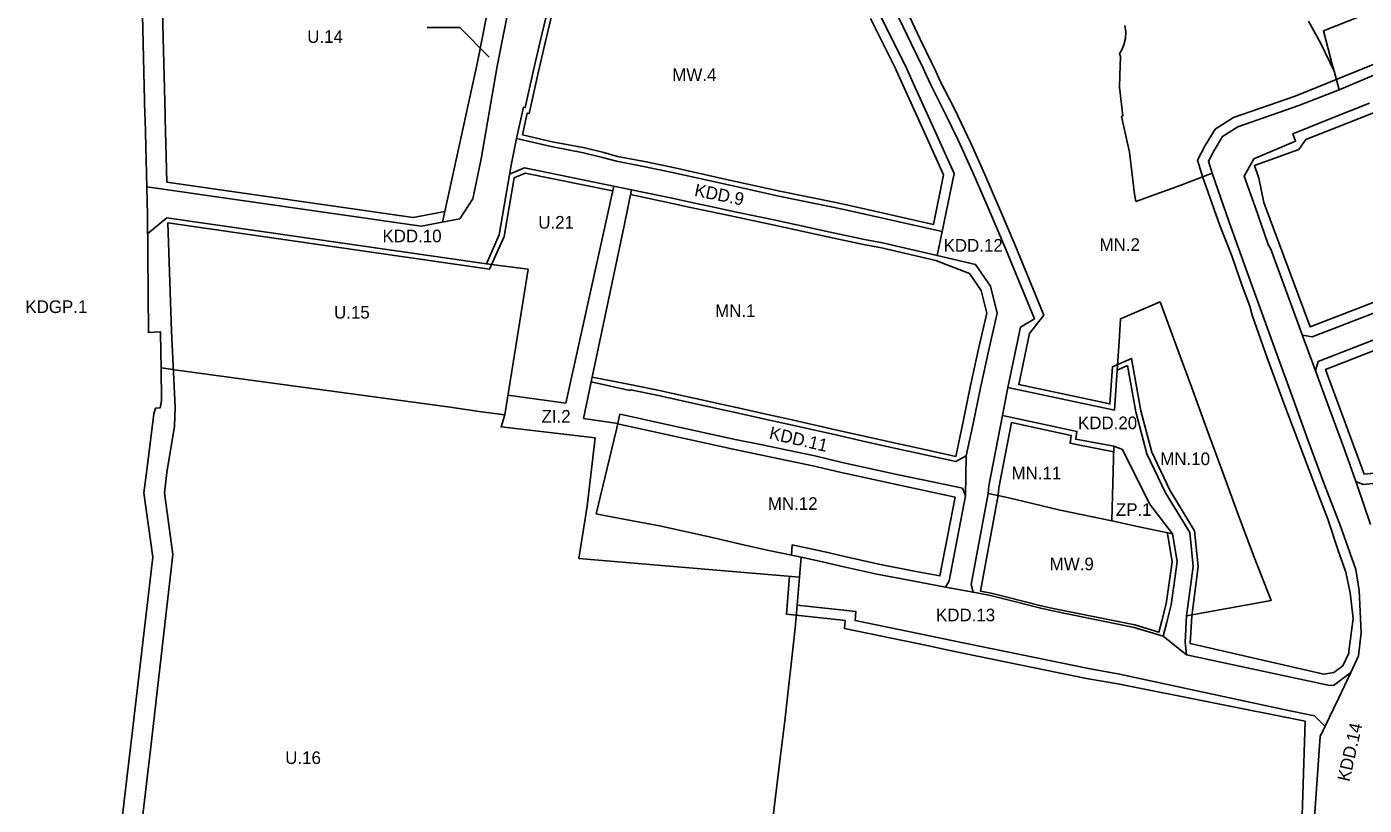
# Model space of a CAD drawing. Extents: x 7428112 to 7429828, y 5548245 to 5549272.
# Drawn here: x 7428745 to 7429274, y 5548641 to 5548949 of the extents above; entities that cross this region are included whole.
import ezdxf

# ---------------------------------------------------------------- set-up
doc = ezdxf.new("R2010")
doc.units = 0
for name, color, linetype in [('LIN_Linia Zabudowy Nieprzekraczalna', 7, 'Continuous'), ('LIN_Linia Zabudowy Obowiązujaca', 7, 'Continuous'), ('LIN_linie_rozgraniczajace', 7, 'Continuous'), ('TXT_oznaczenia_przeznaczen', 7, 'Continuous')]:
    doc.layers.add(name, color=color, linetype=linetype)

msp = doc.modelspace()

# ---------------------------------------------------------------- linework, layer by layer
at = {"layer": 'LIN_Linia Zabudowy Nieprzekraczalna'}
for points in [[(7428952.41, 5548952.95), (7428949.72, 5548941.91), (7428947.26, 5548931.07), (7428943.54, 5548914.42), (7428942.78, 5548914.57), (7428940.96, 5548905.98), (7428952.71, 5548903.26), (7428965.53, 5548900.79), (7428973.08, 5548899), (7428978.56, 5548897.44), (7428989.23, 5548895.36), (7429000.01, 5548893.17), (7429021.64, 5548888.35), (7429042.82, 5548883.66), (7429064.87, 5548879.21), (7429073.94, 5548877.18), (7429103.54, 5548870.51)], [(7429091.97, 5548957.24), (7429098.37, 5548943.91), (7429103.07, 5548934.11), (7429104.37, 5548931.39), (7429106.09, 5548927.52), (7429111.98, 5548915.99), (7429117.02, 5548905.51), (7429118.48, 5548902.35), (7429123.93, 5548890.29), (7429129.7, 5548876.77), (7429135.73, 5548862.5), (7429147.22, 5548834.62), (7429141.55, 5548827.32), (7429137.36, 5548807.14), (7429173.44, 5548799.47), (7429174.4, 5548814.14), (7429181.97, 5548817.47), (7429185.61, 5548796.76), (7429189.96, 5548780.41), (7429197.18, 5548765.35)], [(7429103.54, 5548870.51), (7429107.57, 5548890.15), (7429099.91, 5548907.12), (7429092.03, 5548924.54), (7429088.83, 5548931.62), (7429088.89, 5548931.48), (7429078.59, 5548952.07)], [(7429197.17, 5548765.34), (7429206.93, 5548749.19), (7429208.32, 5548735.11), (7429205.78, 5548715.37), (7429205.15, 5548704.66), (7429258.13, 5548692.49), (7429262.07, 5548693.19), (7429265.55, 5548695.78), (7429267.95, 5548700.83), (7429268.02, 5548701.41), (7429269.69, 5548714.47), (7429268.55, 5548724.63), (7429266.8, 5548732.91), (7429263.77, 5548741.48), (7429259.68, 5548753.78), (7429256.37, 5548762.47), (7429241.9, 5548800.77), (7429235.71, 5548817.76), (7429229.71, 5548834.54), (7429228.83, 5548838.13), (7429225.76, 5548846.21), (7429221.66, 5548858.14), (7429216.9, 5548870.06), (7429210.08, 5548889.5), (7429208.06, 5548896.01), (7429211.17, 5548901.7), (7429215.06, 5548908.2), (7429222.32, 5548912.81), (7429246.76, 5548921.31), (7429270.43, 5548930.94), (7429282.75, 5548935.89)], [(7429293.13, 5548920.77), (7429250.94, 5548904.12), (7429248.16, 5548900.12), (7429230.58, 5548893.78), (7429232.38, 5548888.78), (7429234.4, 5548879.13), (7429252.69, 5548829.93), (7429281.75, 5548841.19)], [(7428976.58, 5548883.75), (7428941.9, 5548890.86), (7428937.6, 5548888.95), (7428933.66, 5548865.79), (7428927.89, 5548852.76), (7428800.51, 5548871.09), (7428801.95, 5548828.23), (7428803.37, 5548798.18), (7428803.16, 5548790.62), (7428800.14, 5548772.25), (7428799.14, 5548764.28), (7428802.54, 5548739.84), (7428793.64, 5548662.49), (7428784.91, 5548588.83)], [(7428800.15, 5548887.3), (7428897.67, 5548873.26), (7428910.15, 5548875.65)], [(7428968.51, 5548810.1), (7428982.07, 5548807.37), (7428984.75, 5548806.9), (7428995.12, 5548804.74), (7428999.78, 5548803.7), (7429014.73, 5548800.43), (7429021.31, 5548798.96), (7429025.02, 5548798.13), (7429036.73, 5548795.54), (7429046.42, 5548793.4), (7429064.85, 5548789.26), (7429077.29, 5548786.36), (7429089.78, 5548783.68), (7429094.68, 5548782.61), (7429112.46, 5548778.7), (7429115.25, 5548791.87), (7429118.25, 5548806.7), (7429121.58, 5548821.76), (7429124.65, 5548835.38), (7429122.39, 5548844.4), (7429117.82, 5548851.13), (7429104.55, 5548856.25), (7429082.97, 5548861.22), (7429075.92, 5548862.55), (7429062.32, 5548865.5), (7429039.97, 5548870.33), (7429022.68, 5548873.99), (7429015.08, 5548875.62), (7429007.44, 5548877.24), (7428999.67, 5548878.88), (7428983.64, 5548882.3)], [(7429273.99, 5548771.63), (7429309.58, 5548775.34), (7429327.36, 5548777.91), (7429341.97, 5548778.88), (7429346.25, 5548778.91), (7429365.33, 5548778.23), (7429395.07, 5548776.65), (7429395.94, 5548791.78), (7429396.25, 5548798.38), (7429396.88, 5548810.65), (7429398.13, 5548829.54), (7429398.89, 5548843.94), (7429359.73, 5548846.77), (7429348.57, 5548847.59), (7429341.93, 5548845.59), (7429332.58, 5548841.75), (7429312.81, 5548833.85), (7429290.54, 5548825.46), (7429258.77, 5548813.12), (7429269.98, 5548782.77), (7429273.99, 5548771.63)], [(7429047.33, 5548739.59), (7429047.67, 5548743.63), (7429060.53, 5548740.86), (7429069, 5548738.93), (7429081.94, 5548736), (7429095.96, 5548733.31), (7429106.13, 5548731.39), (7429112.1, 5548762.6), (7429102.41, 5548764.65), (7429088.89, 5548767.53), (7429066.54, 5548772.43), (7429055.78, 5548774.94), (7429045.63, 5548777.11), (7429034.95, 5548779.31), (7429024.24, 5548781.52), (7429002.63, 5548786.26), (7428991.78, 5548788.62), (7428978.55, 5548791.52)], [(7429174.9, 5548780.49), (7429159.53, 5548783.53), (7429157.62, 5548783.89), (7429158.1, 5548787.01), (7429145.22, 5548789.75), (7429134.47, 5548792.08), (7429129.44, 5548766.22), (7429129.24, 5548763.4), (7429122.13, 5548725.35), (7429126.41, 5548724.56), (7429132.25, 5548723.08), (7429146.26, 5548719.55), (7429151.59, 5548718.37), (7429183.24, 5548711.96), (7429192.83, 5548709.08), (7429194.01, 5548713.59), (7429194, 5548713.58), (7429195.74, 5548720.27), (7429196.78, 5548727.73), (7429196.78, 5548727.73), (7429198.05, 5548736.99), (7429196.18, 5548748.13)], [(7429248.89, 5548615.78), (7429250.64, 5548673.83), (7429176.51, 5548688.6), (7429164.19, 5548690.82), (7429110.08, 5548701.88), (7429101.13, 5548703.76), (7429068.35, 5548710.49), (7429068.6, 5548713.71), (7429067.68, 5548713.81), (7429058.96, 5548714.74), (7429045.34, 5548716.2), (7429046.62, 5548731.26)]]:
    msp.add_lwpolyline(points, dxfattribs=at)
at = {"layer": 'LIN_Linia Zabudowy Obowiązujaca'}
msp.add_lwpolyline([(7428799.47, 5549020.58), (7428799.49, 5549012.24), (7428798.2, 5549005.67), (7428797.09, 5549002.11), (7428797.97, 5548974.77), (7428798.2, 5548965.01), (7428799.48, 5548914.05), (7428799.52, 5548912.51), (7428800.15, 5548887.3)], dxfattribs=at)
at = {"layer": 'LIN_linie_rozgraniczajace'}
for p, q in [((7429179.33, 5548949.21), (7429179.67, 5548946.81)), ((7429179.58, 5548944.17), (7429178.94, 5548941.54)), ((7429179.67, 5548946.81), (7429179.58, 5548944.17)), ((7429178.18, 5548939.67), (7429177.23, 5548938.18)), ((7429178.94, 5548941.54), (7429178.18, 5548939.67)), ((7429264.13, 5548923.82), (7429262.19, 5548931.12)), ((7429264.13, 5548923.82), (7429264.13, 5548923.82)), ((7429178.54, 5548913.46), (7429178.04, 5548913.2)), ((7429178.04, 5548913.2), (7429181.23, 5548899.12)), ((7429181.23, 5548899.12), (7429183.11, 5548882.55)), ((7428958.04, 5548799.71), (7428977.01, 5548885.7)), ((7429183.11, 5548882.55), (7429183.61, 5548879.53)), ((7429133.04, 5548806.01), (7429130.94, 5548794.89)), ((7428935.14, 5548802.98), (7428958.04, 5548799.71)), ((7428965.04, 5548793.69), (7428978.61, 5548791.76)), ((7428969.7, 5548786.07), (7428966.54, 5548759.03)), ((7429116.58, 5548778.86), (7429116.25, 5548763.03)), ((7429194.5, 5548707.58), (7429203.76, 5548700.07))]:
    msp.add_line(p, q, dxfattribs=at)
for points in [[(7428801.64, 5549044.44), (7428807.55, 5549033.16), (7428791.45, 5549025.67), (7428791.49, 5549013.01), (7428790.43, 5549007.64), (7428789.05, 5549003.2), (7428789.97, 5548974.55), (7428790.2, 5548964.82), (7428791.48, 5548913.85), (7428791.52, 5548912.31), (7428792.48, 5548874.26), (7428792.86, 5548827.69), (7428797.62, 5548827.93), (7428797.75, 5548819.85), (7428797.85, 5548813.77), (7428798.06, 5548800.71), (7428797.53, 5548797.93), (7428795.68, 5548797.76), (7428794.98, 5548795.49), (7428792.2, 5548773.24), (7428791.07, 5548764.22), (7428794.62, 5548738.74)], [(7428916.16, 5548872.72), (7428921.26, 5548880.63), (7428924.56, 5548896.44), (7428930.92, 5548933.14), (7428938.98, 5548973.92), (7428938.46, 5548979.7), (7428933.04, 5548984.31)], [(7428792.54, 5548866.94), (7428800.07, 5548873.17), (7428926.67, 5548854.95), (7428931.73, 5548866.37), (7428936.43, 5548894.03), (7428938.59, 5548904.47), (7428941.24, 5548916.93), (7428942.02, 5548916.77), (7428945.31, 5548931.51), (7428947.77, 5548942.37), (7428950.46, 5548953.38), (7428954.97, 5548975.98), (7428959.58, 5548979.15)], [(7428930.12, 5548970.35), (7428923.09, 5548934.77), (7428909.22, 5548871.4)], [(7429262.19, 5548931.12), (7429261.7, 5548932.93), (7429257.95, 5548947.09), (7429296.1, 5548962.3)], [(7429078.04, 5548954.23), (7429082.33, 5548953.54), (7429092.47, 5548933.27)], [(7429088.34, 5548955.56), (7429094.76, 5548942.18), (7429099.46, 5548932.38), (7429100.74, 5548929.71), (7429102.48, 5548925.8), (7429108.4, 5548914.21), (7429113.4, 5548903.8), (7429114.84, 5548900.69), (7429120.27, 5548888.68), (7429126.02, 5548875.21), (7429132.04, 5548860.96), (7429143.52, 5548833.1)], [(7429252.07, 5548950.98), (7429256.96, 5548942.13), (7429262.19, 5548931.12)], [(7429177.23, 5548938.18), (7429177.61, 5548937.03), (7429177.33, 5548929.51), (7429177.16, 5548924.88), (7429178.54, 5548913.46)], [(7429264.13, 5548923.82), (7429288.17, 5548934.01), (7429294.34, 5548936.71), (7429304.31, 5548939.72), (7429307.92, 5548940.81), (7429319.93, 5548941.54), (7429337.32, 5548941.63), (7429352.33, 5548940.31), (7429375.39, 5548937.55), (7429390.3, 5548935.75)], [(7429092.47, 5548933.27), (7429095.67, 5548926.19), (7429103.56, 5548908.77), (7429111.75, 5548890.61), (7429107.04, 5548867.67), (7429105, 5548858.2), (7429120.25, 5548854.67), (7429126.1, 5548846.06), (7429128.76, 5548835.43), (7429125.48, 5548820.89), (7429122.16, 5548805.87), (7429119.17, 5548791.06), (7429116.58, 5548778.86), (7429112.45, 5548776.65)], [(7429252.81, 5548613.18), (7429256.65, 5548667.75), (7429263.83, 5548682.83), (7429268.74, 5548693.16), (7429271.85, 5548699.71), (7429272.91, 5548708.97), (7429272.01, 5548725.58), (7429270.69, 5548733.9), (7429264.62, 5548751.1), (7429257.96, 5548768.42), (7429251.81, 5548785.28), (7429245.66, 5548802.14), (7429239.47, 5548819.12), (7429233.47, 5548835.9), (7429227.3, 5548852.67), (7429220.67, 5548871.39), (7429213.88, 5548890.76), (7429212.38, 5548895.58), (7429214.64, 5548899.71), (7429218.01, 5548905.33), (7429224.07, 5548909.19), (7429248.15, 5548917.56), (7429264.13, 5548923.82)], [(7429264.13, 5548923.82), (7429264.13, 5548923.82)], [(7429276.58, 5548751.73), (7429271.29, 5548767.33), (7429266.22, 5548781.4), (7429260.02, 5548798.19), (7429253.74, 5548815.46), (7429250.35, 5548824.73), (7429243.78, 5548842.42), (7429237.09, 5548860.74), (7429236.09, 5548862.52), (7429230.92, 5548877.45), (7429226.57, 5548889.63), (7429230.4, 5548896.41), (7429246.9, 5548903.52), (7429245.85, 5548906.41), (7429260.88, 5548912.49), (7429276.15, 5548918.48)], [(7429107.04, 5548867.67), (7429084.02, 5548872.86), (7429073.5, 5548875.23), (7429064.45, 5548877.25), (7429042.41, 5548881.7), (7429021.21, 5548886.4), (7428999.59, 5548891.21), (7428988.84, 5548893.4), (7428978.09, 5548895.49), (7428972.58, 5548897.06), (7428965.11, 5548898.83), (7428952.3, 5548901.3), (7428938.59, 5548904.47)], [(7428935.8, 5548890.35), (7428941.68, 5548892.95), (7428984.04, 5548884.26), (7429000.09, 5548880.84), (7429007.85, 5548879.2), (7429015.5, 5548877.58), (7429023.1, 5548875.95), (7429030.8, 5548874.32), (7429040.39, 5548872.29), (7429062.74, 5548867.45), (7429076.32, 5548864.51), (7429083.38, 5548863.18), (7429105, 5548858.2)], [(7429183.61, 5548879.53), (7429200.87, 5548885.83), (7429213.88, 5548890.76)], [(7428916.16, 5548872.72), (7428900.78, 5548869.79), (7428792.2, 5548885.42)], [(7428984.04, 5548884.26), (7428981.28, 5548870.56), (7428968.11, 5548808.21), (7428965.04, 5548793.69)], [(7429249.64, 5548826.66), (7429253.49, 5548825.95), (7429283.25, 5548837.48), (7429301.67, 5548845.25), (7429319.49, 5548851.43), (7429316.63, 5548859.42), (7429335, 5548866.04), (7429352.49, 5548872.08), (7429353.33, 5548864.36), (7429354.17, 5548857.17), (7429384.08, 5548855.2), (7429401.67, 5548854.63), (7429403.59, 5548856.03)], [(7428926.67, 5548854.95), (7428932.66, 5548854.09), (7428943.09, 5548852.76), (7428933.88, 5548795.08)], [(7429403.01, 5548846.11), (7429401.04, 5548847.79), (7429360.02, 5548850.76), (7429348.12, 5548851.63), (7429340.59, 5548849.36), (7429331.08, 5548845.46), (7429311.36, 5548837.58), (7429289.11, 5548829.2), (7429255.79, 5548816.25), (7429254.78, 5548812.6)], [(7429203.78, 5548715.55), (7429237.21, 5548721.6), (7429230.48, 5548738.83), (7429224.31, 5548755.33), (7429218.11, 5548772.37), (7429211.79, 5548789.52), (7429205.65, 5548806.23), (7429199.48, 5548822.97), (7429193.27, 5548839.83), (7429177.6, 5548833.19), (7429177.13, 5548824.18), (7429176.32, 5548812.8)], [(7429133.04, 5548806.01), (7429138, 5548829.88), (7429143.52, 5548833.1)], [(7428797.85, 5548813.77), (7428806.05, 5548812.53), (7428912.23, 5548798.16), (7428923.77, 5548796.52), (7428933.88, 5548795.08)], [(7429180.44, 5548814.61), (7429176.32, 5548812.8), (7429175.28, 5548797.03)], [(7429180.44, 5548814.61), (7429183.66, 5548796.33)], [(7428968.1, 5548808.15), (7428983.42, 5548804.77), (7428983.51, 5548805.09), (7428984.37, 5548804.94), (7428994.7, 5548802.78), (7428999.35, 5548801.75), (7429014.3, 5548798.48), (7429020.87, 5548797.01), (7429024.59, 5548796.18), (7429036.3, 5548793.59), (7429045.98, 5548791.45), (7429064.4, 5548787.31), (7429076.85, 5548784.41), (7429089.36, 5548781.73), (7429094.25, 5548780.66), (7429112.45, 5548776.65)], [(7429133.04, 5548806.01), (7429175.28, 5548797.03)], [(7428933.88, 5548795.08), (7428932.49, 5548790.33), (7428969.7, 5548786.07)], [(7428977.93, 5548788.8), (7428979.44, 5548795.38), (7428981.9, 5548794.88)], [(7429125.51, 5548766.98), (7429125.27, 5548763.93), (7429118.54, 5548727.91), (7429119.27, 5548724.87), (7429108.37, 5548726.9), (7429109.84, 5548729.48), (7429116.25, 5548763.03), (7429115, 5548766.08), (7429103.24, 5548768.56), (7429089.74, 5548771.44), (7429067.42, 5548776.33), (7429056.65, 5548778.84), (7429046.45, 5548781.02), (7429035.76, 5548783.23), (7429025.07, 5548785.43), (7429003.48, 5548790.17), (7428992.63, 5548792.53), (7428981.9, 5548794.88)], [(7429125.51, 5548766.98), (7429130.94, 5548794.89)], [(7429130.94, 5548794.89), (7429145.64, 5548791.71), (7429160.36, 5548788.57), (7429159.89, 5548785.5), (7429174.97, 5548782.71), (7429174.96, 5548782.55)], [(7429183.66, 5548796.33), (7429188.08, 5548779.71)], [(7428977.93, 5548788.8), (7428970.12, 5548755.89), (7428972.58, 5548755.41), (7428983.83, 5548753.28), (7428995.13, 5548751.13), (7429016.58, 5548746.44), (7429027.18, 5548744), (7429037.77, 5548741.57), (7429049.36, 5548739.17), (7429051.27, 5548738.76)], [(7429174.96, 5548782.55), (7429174.39, 5548763.16), (7429174.21, 5548753.11)], [(7429174.97, 5548782.71), (7429178.37, 5548781.47), (7429189.1, 5548759.9), (7429198.22, 5548748.06)], [(7429188.08, 5548779.71), (7429195.46, 5548764.31)], [(7429310.07, 5548771.37), (7429273.68, 5548767.58), (7429270.8, 5548768.68)], [(7429125.27, 5548763.93), (7429132.2, 5548762.48), (7429139.49, 5548760.77), (7429153.7, 5548757.42), (7429174.21, 5548753.11), (7429184.33, 5548750.98), (7429198.22, 5548748.06)], [(7429195.46, 5548764.31), (7429204.99, 5548748.54), (7429206.31, 5548735.14), (7429203.78, 5548715.55), (7429203.18, 5548705.16)], [(7428966.54, 5548759.03), (7428963.2, 5548738.3), (7429050.61, 5548730.93)], [(7429198.76, 5548727.46), (7429200.07, 5548737.02), (7429198.22, 5548748.06)], [(7428770.8, 5548412.3), (7428766.64, 5548415.11), (7428761.95, 5548448.13), (7428760.36, 5548464.3), (7428761.75, 5548484.36), (7428764.67, 5548515.63), (7428765.48, 5548520.73), (7428766.2, 5548526.53), (7428766.02, 5548528.7), (7428766.54, 5548533.82), (7428764.74, 5548534.08), (7428765.44, 5548541.68), (7428767.31, 5548541.41), (7428768.06, 5548548.77), (7428774.55, 5548570.27), (7428776.97, 5548589.79), (7428785.7, 5548663.43), (7428794.62, 5548738.74)], [(7429108.37, 5548726.9), (7429095.21, 5548729.38), (7429081.12, 5548732.08), (7429068.11, 5548735.03), (7429059.67, 5548736.95), (7429051.27, 5548738.76), (7429049.66, 5548719.76), (7429059.38, 5548718.72), (7429068.11, 5548717.79), (7429072.89, 5548717.27), (7429072.61, 5548713.7), (7429101.94, 5548707.68), (7429110.89, 5548705.8), (7429164.94, 5548694.75), (7429177.22, 5548692.54), (7429241.53, 5548678.66), (7429254.36, 5548676.04), (7429258.57, 5548671.77)], [(7429195.94, 5548713.08), (7429197.71, 5548719.88), (7429198.76, 5548727.46)], [(7429195.94, 5548713.08), (7429194.49, 5548707.54), (7429183, 5548710.99), (7429151.38, 5548717.39), (7429146.03, 5548718.58), (7429132.01, 5548722.11), (7429126.2, 5548723.58), (7429119.27, 5548724.87)], [(7429049.66, 5548719.76), (7429048.89, 5548710.74), (7429044.7, 5548673.94), (7429042.94, 5548659.17), (7429034.04, 5548585.96), (7429026.55, 5548526.32), (7429025.62, 5548517.96), (7429007.68, 5548519.94), (7428922.28, 5548529.44), (7428845.59, 5548539.14), (7428829.43, 5548541.08), (7428779.2, 5548547.16), (7428768.06, 5548548.76)], [(7429268.74, 5548693.16), (7429261.85, 5548688.05), (7429259.82, 5548688.16), (7429203.76, 5548700.07), (7429203.18, 5548705.16)]]:
    msp.add_lwpolyline(points, dxfattribs=at)
at = {"layer": 'TXT_oznaczenia_przeznaczen'}
msp.add_lwpolyline([(7428903.2, 5548948.52), (7428916.09, 5548948.52), (7428927.69, 5548936.78)], dxfattribs=at)

# ---------------------------------------------------------------- texts
for s, p in [('U.14', (7428855.7, 5548942.38)), ('MW.4', (7429000.19, 5548927.25)), ('U.21', (7428947.15, 5548868.86)), ('KDD.10', (7428885.47, 5548863.44)), ('KDD.12', (7429107.58, 5548859.74)), ('MN.2', (7429169.32, 5548860.05)), ('KDGP.1', (7428744.13, 5548835.44)), ('U.15', (7428866.32, 5548833.21)), ('MN.1', (7429017.15, 5548833.86)), ('ZI.2', (7428948.43, 5548792.03)), ('KDD.20', (7429160.78, 5548789.46)), ('MN.10', (7429193.35, 5548775.24)), ('MN.11', (7429134.48, 5548769.58)), ('MN.12', (7429038.02, 5548757.52)), ('ZP.1', (7429175.79, 5548755.15)), ('MW.9', (7429149.58, 5548733.59)), ('KDD.13', (7429104.58, 5548713.41)), ('U.16', (7428846.99, 5548656.91))]:
    msp.add_text(s, height=5, dxfattribs=at).set_placement(p)
for s, rotation, p in [('KDD.9', 348.5646, (7429008.68, 5548881.84)), ('KDD.11', 346.8948, (7429038.24, 5548785.73)), ('KDD.14', 77.2963, (7429268.22, 5548649.68))]:
    msp.add_text(s, height=5, rotation=rotation, dxfattribs=at).set_placement(p)

doc.saveas('drawing.dxf')
